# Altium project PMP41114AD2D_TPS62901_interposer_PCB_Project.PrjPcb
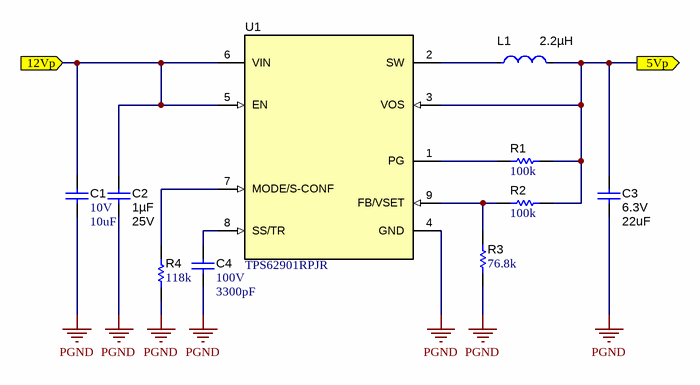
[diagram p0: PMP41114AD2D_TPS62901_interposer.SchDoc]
CopyrightYear: 2024; PCB_Layout: Richard Yin; PCB_Rev: E1; PRJ_Customer: Public Release; PRJ_Engineer: Richard Yin; PRJ_Number: PMP41114AD2D_TPS62901_interposer; PRJ_Title: PMP41114AD2D_TPS62901_interposer; SCH_Rev: E1; TechSupport: http://www.ti.com/support; TID: N/A
1 sheet, 10 parts. Net scope: flat (ports and power ports of the same name join across sheets).
Board file: PMP41114AD2D_TPS62901_interposer_PCB_Project.PcbDoc

## Sheet PMP41114AD2D_TPS62901_interposer.SchDoc
size A4; Date: Not shown in title block; ApprovedBy: Not shown in title block; CheckedBy: Not shown in title block; Author: Not shown in title block; CompanyName: Not shown in title block; Engineer: Not shown in title block; Organization: Not shown in title block; Address1: Not shown in title block; Address2: Not shown in title block; Address3: Not shown in title block; Address4: Not shown in title block; DocumentNumber: 1; Revision: Use project parameter SCH_Rev; SheetNumber: 1; SheetTotal: 1; PageSetup: Record=PageOptions¦CenterHorizontal=True¦CenterVertical=True¦PrintScale=0.93¦XCorrection=1.00¦YCorrection=1.00¦PrintKind=0¦BorderSize=5000000¦LeftOffset=0¦BottomOffset=0¦Orientation=2¦PaperLength=1000¦PaperWidth=1000¦Scale=100¦PaperSource=15¦PrintQuality=600¦MediaType=1¦DitherType=10¦PaperKind=Letter¦PrintScaleMode=1

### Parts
C1  VDC_V: 10V  ValueDisplayed: 10uF  [1206]  (hidden comment: C3216X7R1A106M160AC)
C2  Cap_F: 1µF  VDC_V: 25V  [0805_HV]  (hidden comment: C0805C105K3RACTU)
C3  VDC_V: 6.3V  ValueDisplayed: 22uF  [0805_HV]  (hidden comment: CL21A226KQQNNNE)
C4  VDC_V: 100V  ValueDisplayed: 3300pF  [0402]  (hidden comment: GRM155R72A332KA01D)
L1  Ind_H: 2.2µH  [FP-74438336010_SMD2-MFG]  (hidden comment: 74438336022)
R1  ValueDisplayed: 100k  [0402]  (hidden comment: RC0402FR-07100KL)
R2  ValueDisplayed: 100k  [0402]  (hidden comment: RC0402FR-07100KL)
R3  ValueDisplayed: 76.8k  [0402]  (hidden comment: CRCW040276K8FKED)
R4  ValueDisplayed: 118k  [0603]  (hidden comment: CRCW0603118KFKEA)
U1  TPS62901RPJR  [RPJ0009A]

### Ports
5Vp (out), 12Vp (in)

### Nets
PGND: C1.2 C2.2 C3.2 C4.2 R3.1 R4.1 U1.4(GND)
5Vp: C3.1 L1.2 R1.2 R2.2 U1.3(VOS) ; port 5Vp
12Vp: C1.1 C2.1 U1.5(EN) U1.6(VIN) ; port 12Vp
NetC4_1: C4.1 U1.8(SS/TR)
NetL1_1: L1.1 U1.2(SW)
NetR1_1: R1.1 U1.1(PG)
NetR2_1: R2.1 R3.2 U1.9(FB/VSET)
NetR4_2: R4.2 U1.7(MODE/S-CONF)

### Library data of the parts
C1 = CMP-0008689-2: CAP, CERM, 10 uF, 10 V, +/- 20%, X7R, 1206; Manufacturer: TDK; TaMin_C: -55°C; ESR_ohm: 4.6m; Polarized: N; SizeAreaWB_mm2: 10.92; Value1: 0.0046 ohm; U/M: EA; Value: 10uF; TaMax_C: 125°C; SizeZ_mm: 1.35; SizeX_mm: 3.2; SizeY_mm: 1.6; SizeArea_mm2: 5.12; CompType: Capacitor; Cap_F: 10µF; AEC Category: Q200
C2 = CMP-0007728-2: CAP, CERM, 1 uF, 25 V, +/- 10%, X7R, 0805; Manufacturer: Kemet; TaMin_C: -55°C; Polarized: N; SizeAreaWB_mm2: 6.75; Value1: Unknown; U/M: EA; Value: 1uF; TaMax_C: 125°C; SizeZ_mm: 1.45; SizeX_mm: 2; SizeY_mm: 1.25; Cap_Case: 0805; SizeArea_mm2: 2.5; CompType: Capacitor; AEC Category: Q200
C3 = CMP-0007989-2: CAP, CERM, 22 uF, 6.3 V, +/- 10%, X5R, 0805; Manufacturer: Samsung Electro-Mechanics; TaMin_C: -55°C; Polarized: N; SizeAreaWB_mm2: 6.75; Value1: Unknown; U/M: EA; Value: 22uF; TaMax_C: 85°C; SizeZ_mm: 1.45; SizeX_mm: 2; SizeY_mm: 1.25; Cap_Case: 0805; SizeArea_mm2: 2.5; CompType: Capacitor; Cap_F: 22µF; AEC Category: Q200
C4 = CMP-0006708-2: CAP, CERM, 3300 pF, 100 V, +/- 10%, X7R, 0402; Manufacturer: MuRata; TaMin_C: -55°C; Polarized: N; SizeAreaWB_mm2: 3; Value1: Unknown; U/M: EA; Value: 3300pF; TaMax_C: 125°C; SizeZ_mm: 0.6; SizeX_mm: 1; SizeY_mm: 0.5; Cap_F: 3.3nF; AEC Category: Q200
L1 = CMP-0087867-1: 2.2µH Shielded Molded Inductor 2.4A 67mOhm Max 2-SMD; Manufacturer: Wurth Electronics; SizeZ_mm: 2mm; Material: Metal Composite; Isat: 4.3A; Symbol Name: SYM-74438336010; DCR_ohm: 0.032; AEC Grade: Grade 1; AEC Qualified: Yes
R1 R2 = CMP-0026721-1: RES, 100 k, 1%, 0.0625 W, 0402; Manufacturer: Yageo America; Power_W: 62.5mW; TempCo: 100 ppm/C; U/M: EA; Value: 100k; EIA_Code: E96; SizeX_mm: 1; SizeY_mm: 0.5; SizeZ_mm: 0.6; CompType: Resistor; AEC Qualified: N; VDC_V: 50V; AEC Category: Q200
R3 = CMP-0026547-2: RES, 76.8 k, 1%, 0.063 W, AEC-Q200 Grade 0, 0402; Manufacturer: Vishay-Dale; Power_W: 63mW; TempCo: 100 ppm/C; Value_Code: 76k8; Value: 76.8k; EIA_Code: E96; SizeX_mm: 1; SizeY_mm: 0.5; SizeZ_mm: 0.6; Value2: 0.063W; CompType: Resistor; AEC Qualified: Y; VDC_V: 50V; AEC Category: Q200; AEC Grade: 0
R4 = CMP-0022014-4: RES, 118 k, 1%, 0.1 W, AEC-Q200 Grade 0, 0603; Manufacturer: Vishay-Dale; Power_W: 100mW; TempCo: 100 ppm/C; Value: 118k; EIA_Code: E96; SizeX_mm: 1.6; SizeY_mm: 0.8; SizeZ_mm: 1; Value2: 0.1W; SizeArea_mm2: 1.28; CompType: Resistor; AEC Qualified: Y; VDC_V: 75V; AEC Category: Q200; AEC Grade: 0
U1 = CMP-0084864-4: 2.9-V to 18-V, 4-A Synchronous Buck Converters, RPJ0009A (VQFN-HR-9); Manufacturer: Texas Instruments; Alternate PartNumber: TPS62901RPJT; SizeAreaWB_mm2: 7.5; CompType: IC; SizeY_mm: 2; SizeArea_mm2: 3; SizeZ_mm: 1; AEC Qualified: N; SizeX_mm: 1.5; AEC Category: Q200

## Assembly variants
001: all parts fitted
